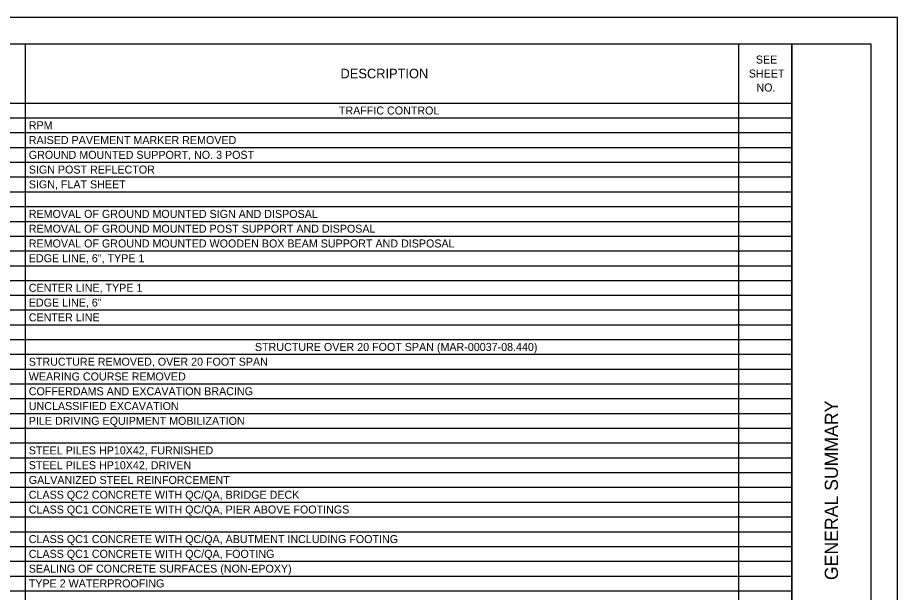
# Model space of a CAD drawing. Extents: x 0 to 34, y 0 to 22.
# Drawn here: x 17.35 to 34, y 11.11 to 22 of the extents above; entities that cross this region are included whole.
import ezdxf

# ---------------------------------------------------------------- set-up
doc = ezdxf.new("R2010")
doc.units = 0
for name, color, linetype in [('Default', 7, 'Continuous'), ('SH_Border', 7, 'Continuous'), ('SH_Cut_Line', 7, 'Continuous'), ('SH_Data', 7, 'Continuous')]:
    doc.layers.add(name, color=color, linetype=linetype)

msp = doc.modelspace()

# ---------------------------------------------------------------- linework, layer by layer
at = {"layer": 'Default'}
for p, q in [((1.5, 21.5), (32, 21.5)), ((17.491, 21.5), (17.491, 0.502)), ((30.995, 21.5), (30.995, 0.502)), ((32, 21.5), (32, 0.502)), ((1.5, 20.38), (32, 20.38)), ((1.5, 20.1), (32, 20.1)), ((1.5, 19.82), (32, 19.82)), ((1.5, 19.54), (32, 19.54)), ((1.5, 19.26), (32, 19.26)), ((1.5, 18.98), (32, 18.98)), ((1.5, 18.7), (32, 18.7)), ((1.5, 18.42), (32, 18.42)), ((1.5, 18.14), (32, 18.14)), ((1.5, 17.86), (32, 17.86)), ((1.5, 17.58), (32, 17.58)), ((1.5, 17.3), (32, 17.3)), ((1.5, 17.021), (32, 17.021)), ((1.5, 16.741), (32, 16.741)), ((1.5, 16.461), (32, 16.461)), ((1.5, 16.181), (32, 16.181)), ((1.5, 15.901), (32, 15.901)), ((1.5, 15.621), (32, 15.621)), ((1.5, 15.341), (32, 15.341)), ((1.5, 15.061), (32, 15.061)), ((1.5, 14.781), (32, 14.781)), ((1.5, 14.501), (32, 14.501)), ((1.5, 14.221), (32, 14.221)), ((1.5, 13.941), (32, 13.941)), ((1.5, 13.661), (32, 13.661)), ((1.5, 13.381), (32, 13.381)), ((1.5, 13.101), (32, 13.101)), ((1.5, 12.821), (32, 12.821)), ((1.5, 12.541), (32, 12.541)), ((1.5, 12.261), (32, 12.261)), ((1.5, 11.981), (32, 11.981)), ((1.5, 11.701), (32, 11.701)), ((1.5, 11.421), (32, 11.421)), ((1.5, 11.141), (32, 11.141))]:
    msp.add_line(p, q, dxfattribs=at)
at = {"layer": 'SH_Border'}
msp.add_line((32, 0.5), (32, 21.5), dxfattribs=at)
msp.add_lwpolyline([(1.5, 21.5), (33.5, 21.5), (33.5, 0.5), (1.5, 0.5)], close=True, dxfattribs=at)
at = {"layer": 'SH_Cut_Line'}
msp.add_lwpolyline([(0, 0), (34, 0), (34, 22), (0, 22)], close=True, dxfattribs=at)

# ---------------------------------------------------------------- texts
at = {"layer": 'Default'}
for s, height, p in [('SEE ', 0.1515, (31.32, 21.129)), ('DESCRIPTION', 0.18181, (23.458, 20.849)), ('SHEET ', 0.1515, (31.187, 20.864)), ('NO.', 0.1515, (31.331, 20.599)), ('TRAFFIC CONTROL', 0.15151, (23.427, 20.164)), ('RPM', 0.1515, (17.557, 19.884)), ('RAISED PAVEMENT MARKER REMOVED', 0.15151, (17.557, 19.604)), ('GROUND MOUNTED SUPPORT, NO. 3 POST', 0.15151, (17.557, 19.324)), ('SIGN POST REFLECTOR', 0.15151, (17.557, 19.045)), ('SIGN, FLAT SHEET', 0.15151, (17.557, 18.765)), ('REMOVAL OF GROUND MOUNTED SIGN AND DISPOSAL', 0.15151, (17.557, 18.205)), ('REMOVAL OF GROUND MOUNTED POST SUPPORT AND DISPOSAL', 0.15151, (17.557, 17.925)), ('REMOVAL OF GROUND MOUNTED WOODEN BOX BEAM SUPPORT AND DISPOSAL', 0.15151, (17.557, 17.645)), ('EDGE LINE, 6", TYPE 1', 0.15151, (17.557, 17.365)), ('CENTER LINE, TYPE 1', 0.15151, (17.557, 16.805)), ('EDGE LINE, 6"', 0.15151, (17.557, 16.525)), ('CENTER LINE', 0.15151, (17.557, 16.245)), ('STRUCTURE OVER 20 FOOT SPAN (MAR-00037-08.440)', 0.15151, (21.838, 15.685)), ('STRUCTURE REMOVED, OVER 20 FOOT SPAN', 0.15151, (17.557, 15.405)), ('WEARING COURSE REMOVED', 0.15151, (17.557, 15.125)), ('COFFERDAMS AND EXCAVATION BRACING', 0.15151, (17.557, 14.845)), ('UNCLASSIFIED EXCAVATION', 0.15151, (17.557, 14.565)), ('PILE DRIVING EQUIPMENT MOBILIZATION', 0.15151, (17.557, 14.285)), ('STEEL PILES HP10X42, FURNISHED', 0.15151, (17.557, 13.725)), ('STEEL PILES HP10X42, DRIVEN', 0.15151, (17.557, 13.445)), ('GALVANIZED STEEL REINFORCEMENT', 0.15151, (17.557, 13.165)), ('CLASS QC2 CONCRETE WITH QC/QA, BRIDGE DECK', 0.15151, (17.557, 12.885)), ('CLASS QC1 CONCRETE WITH QC/QA, PIER ABOVE FOOTINGS', 0.15151, (17.557, 12.605)), ('CLASS QC1 CONCRETE WITH QC/QA, ABUTMENT INCLUDING FOOTING', 0.15151, (17.557, 12.045)), ('CLASS QC1 CONCRETE WITH QC/QA, FOOTING', 0.15151, (17.557, 11.765)), ('SEALING OF CONCRETE SURFACES (NON-EPOXY)', 0.15151, (17.557, 11.485)), ('TYPE 2 WATERPROOFING', 0.15151, (17.557, 11.205))]:
    msp.add_text(s, height=height, dxfattribs=at).set_placement(p)
at = {"layer": 'SH_Data'}
msp.add_text('GENERAL SUMMARY', height=0.25, rotation=90, dxfattribs=at).set_placement((32.875, 11.344))

doc.saveas('drawing.dxf')
